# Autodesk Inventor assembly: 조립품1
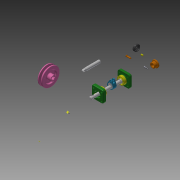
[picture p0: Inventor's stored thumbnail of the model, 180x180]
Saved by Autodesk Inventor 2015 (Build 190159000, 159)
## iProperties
Created: 2021-08
Part Number: 조립품1
Document SubType Name: Assembly
Designer: 10462
Author: 10462
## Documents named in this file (16)
- C:\Users\10462\Desktop\710806V1029\조립품1.iam
- C:\Users\10462\Desktop\710806V1029\V벨트풀리.ipt
- C:\Users\10462\Desktop\710806V1029\고정핀 1.2x8.ipt
- C:\Users\10462\Desktop\710806V1029\뒤커버.ipt
- C:\Users\10462\Desktop\710806V1029\링크.ipt
- C:\Users\10462\Desktop\710806V1029\멈춤나사 M3x8.ipt
- C:\Users\10462\Desktop\710806V1029\베어링 12x32x10.ipt
- C:\Users\10462\Desktop\710806V1029\본체.ipt
- C:\Users\10462\Desktop\710806V1029\볼트 M4.ipt
- C:\Users\10462\Desktop\710806V1029\부시.ipt
- C:\Users\10462\Desktop\710806V1029\슬라이드.ipt
- C:\Users\10462\Desktop\710806V1029\앞커버.ipt
- C:\Users\10462\Desktop\710806V1029\오일 실 12 25 7.ipt
- C:\Users\10462\Desktop\710806V1029\키 4x4x10.ipt
- C:\Users\10462\Desktop\710806V1029\편심축.ipt
- C:\Users\10462\Desktop\710806V1029\핀 5x18.ipt
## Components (3 placed, 3 different names)
1. V벨트풀리:1
2. 고정핀 1.2x8:1
3. 핀 5x18:1
